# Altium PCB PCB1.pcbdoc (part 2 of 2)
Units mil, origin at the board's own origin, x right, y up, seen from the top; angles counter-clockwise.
Board outline 26305 x 7340 mil, 4 copper layers (Top Layer, Inner1, Inner2, Bottom Layer); 215 components, 225 nets, 1133 pads, 8 vias.
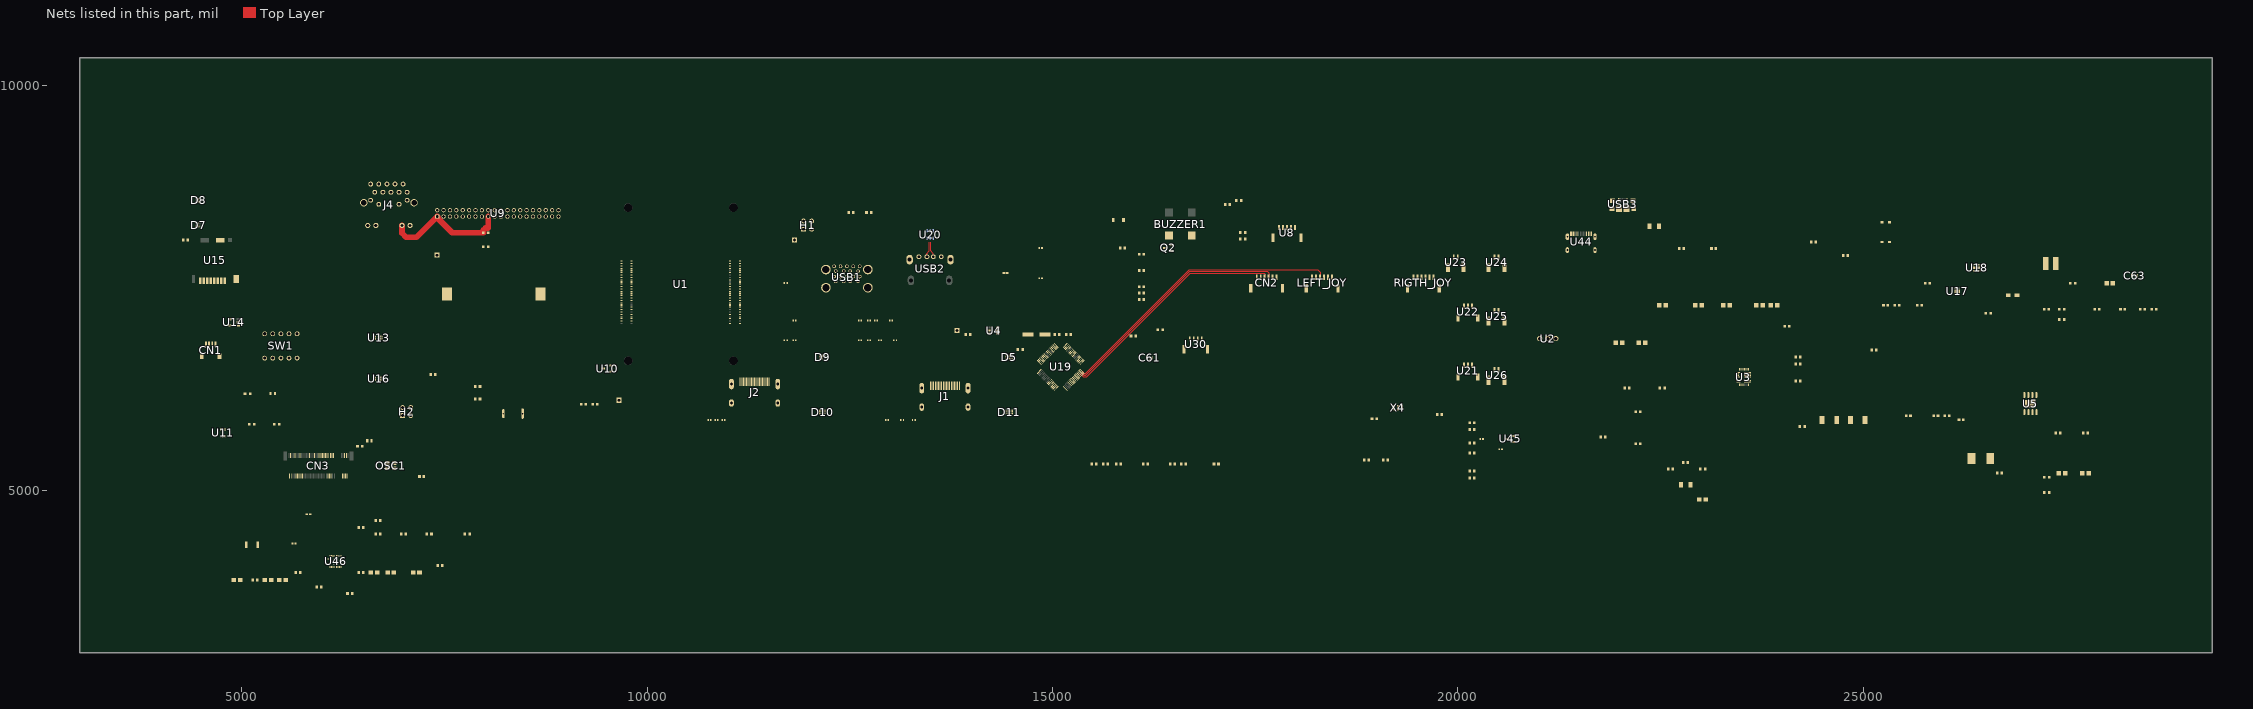
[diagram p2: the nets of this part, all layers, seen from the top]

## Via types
v1: diameter 15.75, hole 7.87, Top Layer to Bottom Layer, 8 vias

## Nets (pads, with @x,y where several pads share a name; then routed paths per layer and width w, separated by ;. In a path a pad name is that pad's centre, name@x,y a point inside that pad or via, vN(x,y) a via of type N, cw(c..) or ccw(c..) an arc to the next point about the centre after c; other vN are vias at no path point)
5V_USB3.0: C20.1 C21.2 C22.2 C64.1 U4.6 U20.5 USB1.1 USB1.10 USB2.1
$1N18: J1.14
$1N31: J2.14
$1N87: U1.141
$1N88: U1.139
$1N121: R8.2 U4.5
$1N122: U1.107 U1.113 U1.119 U1.125 U1.131 U1.137 U1.155 U1.161 U1.167 U1.173 U1.179 U1.185 U1.191 U1.197
$1N155: R36.2 U20.4
$1N156: R37.1 U20.6
$2N9: R1.2 U3.25
$2N10: C5.2 R1.1
$2N12: C6.2 R2.2 U3.2
$2N29: R4.2 U3.5
$2N30: C10.1 R5.2 U3.30
$2N31: C10.2 R6.2 U3.29
$2N37: C12.2 U3.26
$2N45: D1.1 U44.A4B9 U44.B4A9
$2N54: C50.2 D2.1 D3.1 U18.2 U18.3
$2N57: L4.1 U18.9
$2N58: C51.2 C63.1 L4.2 R30.2 U18.10
$2N59: R30.1 U18.7
$2N68: L1.1 U17.6
$2N83: C23.2 U5.4
$2N84: C26.2 U5.3
$2N89: C30.2 U5.7
$2N91: C30.1 L3.1 U5.6
$2N3270: C67.2 U46.10
$2N3397: C68.2 U46.8
$2N3401: C68.1 R41.1 U46.4 U46.5 U46.6 U46.7 U47.2
$2N3574: R41.2 U46.3
$2N3583: R42.2 U46.19
$2N4443: C77.2 U46.1
$2N4479: C80.2 R43.1 U46.18
$2N4576: C75.1 R43.2
$2N4875: C69.2 C71.2 C74.2 C79.2 R47.1 U46.14 U46.15 U46.16
$2N4890: R44.1 R45.1 R46.1 R47.2 U46.17 U48.1
$3N7: U1.18
$3N25: U1.64
$3N62: J3.1 U1.73
$3N114: R11.2 RED_LED.2
$3N115: R11.1 U11.4
$3N118: GREEN_LED.2 R13.2
$3N153: C40.2 J4.4 J4.5
$3N161: J4.16 R23.1
$3N162: J4.18 R24.2
$3N198: CN3.10 R31.2
$3N199: GREEN_LED1.2 R31.1
$3N203: CN3.68 OSC1.3
$4N7: U19.5 X4.1
$4N8: U19.6 X4.3
$4N9: R28.2 U19.60
$4N11: R29.2 U19.7
$4N13: C59.2 U19.47
$4N14: C60.2 U19.31
$4N18: C61.1 U30.1
$4N99: R12.2 R19.2 U45.1
$4N103: Q2.1 R40.2
$4N108: BUZZER1.2 D4.2 Q2.3
$4N114: R20.2 U8.3
$4N115: R34.2 U8.2
+1.8V: R22.1 U1.88 U1.90
+3.3V: GREEN_LED.1 J4.15 J4.17 R21.1 RED_LED.1 U1.84 U1.86 U9.1 U9.17 U11.5 U14.5 U19.8 U46.2 | length 1562.8
  Top Layer w70.87: J4.17@6976.02,8270.08 6974.89,8268.95 6974.89,8175.11 7025,8125 7156.14,8125 U9.1@7410.41,8379.27 7422.14,8367.54 7422.14,8351.52 7594.96,8178.7 R21.1@7978.78,8178.7 7980.81,8180.73 7980.81,8212.86 8005.07,8237.12 8037.2,8237.12 8040.33,8240.25 U9.17@8040.33,8379.27
+5V_RT: C31.2 C32.2 C33.2 C41.2 C42.2 C43.2 L3.2 R9.2 U12.1 U17.3 USB3.1
ACOK: R16.1 U3.28 U19.10
ADC1_IN0: C34.1 CN2.3 U19.14 | length 2875.4
  Top Layer w10: U19.14@15337.06,6441.72 15376.57,6402.21 15419.19,6402.21 15940.7,6923.72 15940.7,6928.14 15947.13,6934.58 15951.55,6934.58 16700,7683.02 17609.52,7683.02 17616.59,7675.95 CN2.3@17616.59,7632.48
ADC1_IN1: C35.1 CN2.4 U19.15 | length 2918.7
  Top Layer w10: U19.15@15350.98,6455.63 15384.72,6421.89 15411.03,6421.89 16691.85,7702.7 17647.2,7702.7 17665.8,7684.1 CN2.4@17665.8,7632.48
ADC1_IN2: C36.1 LEFT_JOY.3 U19.16 | length 3549.6
  Top Layer w10: U19.16@15364.9,6469.56 15392.88,6441.58 15402.88,6441.58 16683.69,7722.39 18270.04,7722.39 18300.18,7692.26 LEFT_JOY.3@18300.18,7632.48
ADC1_IN3: C62.1 LEFT_JOY.4 U19.17
ADC1_IN4: C38.1 RIGTH_JOY.3 U19.20
ADC1_IN5: C37.1 RIGTH_JOY.4 U19.21
AGND: B1.2 C1.1 C2.1 C3.1 C4.1 C5.1 C6.1 C11.1 C12.1 C13.1 C14.1 C15.1 C16.1 C17.1 C18.1 C19.1 C20.2 C21.1 C22.1 C23.1 C24.1 C25.1 C26.1 C27.1 C28.1 C29.1 C32.1 C33.1 C34.2 C35.2 C36.2 C37.2 C38.2 C39.1 C40.1 C41.1 C42.1 C43.1 C45.1 C46.1 C47.1 C48.1 C49.1 C50.1 C51.1 C52.1 C53.1 C54.1 C55.1 C56.1 C57.1 C58.1 C59.1 C60.1 C61.2 C62.2 C63.2 C64.2 C65.1 C66.2 C67.1 C69.1 C70.1 C71.1 C72.1 C73.1 C74.1 C75.2 C77.1 C78.1 C79.1 C80.1 CN1.2 CN1.5 CN1.6 CN2.5 CN2.6 CN2.7 CN2.8 CN3.3 CN3.9 CN3.15 CN3.27 CN3.33 CN3.39 CN3.45 CN3.51 CN3.57 CN3.71 CN3.73 D5.3 D5.8 D7.3 D7.8 D8.3 D8.8 D9.3 D9.8 D10.3 D10.8 D11.3 D11.8 J1.2 J1.5 J1.8 J1.11 J1.17 J1.SH1 J1.SH2 J1.SH3 J1.SH4 J2.2 J2.5 J2.8 J2.11 J2.17 J2.SH1 J2.SH2 J2.SH3 J2.SH4 J4.S1 J4.S2 LEFT_JOY.5 LEFT_JOY.6 LEFT_JOY.7 LEFT_JOY.8 OSC1.2 Q2.2 R3.2 R4.1 R8.1 R10.1 R19.1 R25.1 R27.1 R28.1 R39.2 R42.1 R44.2 R45.2 R46.2 RIGTH_JOY.5 RIGTH_JOY.6 RIGTH_JOY.7 RIGTH_JOY.8 SW1.1 SW1.2 SW1.3 SW1.4 SW1.5 TP2.1 U1.1 U1.2 U1.7 U1.8 U1.13 U1.14 U1.22 U1.23 U1.32 U1.33 U1.42 U1.43 U1.52 U1.53 U1.59 U1.60 U1.65 U1.66 U1.71 U1.74 U1.98 U1.108 U1.114 U1.120 U1.126 U1.132 U1.138 U1.144 U1.150 U1.156 U1.162 U1.168 U1.174 U1.180 U1.186 U1.192 U1.198 U2.1 U3.4 U3.19 U3.27 U4.2 U5.5 U5.9 U6.1 U7.1 U8.1 U8.4 U8.6 U8.7 U9.6 U9.9 U9.14 U9.20 U9.25 U9.30 U9.34 U9.39 U10.3 U11.3 U13.3 U13.8 U14.2 U15.6 U15.9 U15.10 U16.3 U16.8 U17.4 U17.8 U17.9 U18.1 U18.4 U18.5 U18.6 U18.11 U19.12 U19.18 U19.63 U20.2 U21.2 U21.4 U21.5 U22.2 U22.4 U22.5 U23.2 U23.3 U23.4 U24.2 U24.3 U24.4 U25.2 U25.3 U25.4 U26.2 U26.3 U26.4 U27.1 U28.1 U29.1 U30.2 U30.5 U30.6 U31.1 U32.1 U33.1 U34.1 U35.1 U36.1 U37.1 U38.1 U39.1 U40.1 U41.1 U42.1 U43.1 U44.1 U44.2 U44.3 U44.4 U44.A1B12 U44.B1A12 U45.2 U46.11 U46.12 U46.20 U46.21 U48.2 USB1.4 USB1.7 USB1.13 USB1.16 USB1.19 USB1.20 USB2.4 USB2.5 USB2.6 USB3.5 USB3.6 X4.2
  other v1: 6135.86,4095.12 6177.2,4095.12 6106.33,4125.63 6135.86,4125.63 6177.2,4125.63 6206.73,4125.63 6135.86,4156.14 6177.2,4156.14
BST1: C7.2 U3.23
BST2: C8.2 U3.24
BST3: C9.2 U3.15
BT_NDISABLE: SW1.6 U1.91
CC1: U1.94 U44.A5
CC2: U1.96 U44.B5
CM5_GPIO_IN: U1.25 U9.40 U19.9
CM_5V: C1.2 C19.2 C65.2 CN1.4 TP1.1 U1.77 U1.79 U1.81 U1.83 U1.85 U1.87 U4.1 U9.2 U9.4 U10.1 U12.2
D+: U20.1 USB2.3 | length 189.9
  Top Layer w10: 13497.38,8060.91 13497.38,7955.33 13528.75,7923.96 USB2.3@13528.75,7883.96
D-: U20.3 USB2.2 | length 189.9
  Top Layer w10: USB2.2@13450.01,7883.96 13450.01,7923.96 13481.38,7955.33 13481.38,8060.91
EEPROM_NWP: SW1.9 U1.20
EN_5V: U5.1 U19.25
ETH_LEDG: R24.1 U1.17
ETH_LEDY: R23.2 U1.15
FB: C44.1 R26.1 R27.2 U17.1
FB1: C31.1 R9.1 R10.2 U5.2
GPIO2: U1.58 U9.3
GPIO3: U1.56 U9.5
GPIO4: U1.54 U9.7
GPIO5: U1.34 U9.29
GPIO6: U1.30 U9.31
GPIO7: U1.37 U9.26
GPIO8: U1.39 U9.24
GPIO9: U1.40 U9.21
GPIO10: U1.44 U9.19
GPIO11: U1.38 U9.23
GPIO12: U1.31 U9.32
GPIO13: U1.28 U9.33
GPIO14: U1.55 U9.8 U19.42
GPIO15: U1.51 U9.10 U19.43
GPIO16: U1.29 U9.36 U19.45
GPIO17: U1.50 U9.11 U19.44
GPIO18: U1.49 U9.12
GPIO19: U1.26 U9.35
GPIO20: U1.27 U9.38
GPIO22: U1.46 U9.15
GPIO23: U1.47 U9.16
GPIO24: U1.45 U9.18
GPIO25: U1.41 U9.22
GPIO26: U1.24 U9.37
GPIO27: U1.48 U9.13
GPIO_IN0: U19.61 U21.1
GPIO_IN1: U19.62 U21.3
GPIO_IN2: U19.29 U22.1
GPIO_IN3: U19.30 U22.3
GPIO_IN4: U19.33 U23.1
GPIO_IN5: U19.34 U24.1
GPIO_IN6: U19.35 U25.1
GPIO_IN7: U19.36 U26.1
GPIO_VREF: R14.2 R15.2 R21.2 R22.2 U1.78
HDMI0_CEC: J1.13 U1.151 U42.2
HDMI0_CK_N: D11.5 D11.6 J1.12 U1.190
HDMI0_CK_P: D11.4 D11.7 J1.10 U1.188
HDMI0_D0_N: D11.2 D11.9 J1.9 U1.184
HDMI0_D0_P: D11.1 D11.10 J1.7 U1.182
HDMI0_D1_N: D5.5 D5.6 J1.6 U1.178
HDMI0_D1_P: D5.4 D5.7 J1.4 U1.176
HDMI0_D2_N: D5.2 D5.9 J1.3 U1.172
HDMI0_D2_P: D5.1 D5.10 J1.1 U1.170
HDMI0_HOTPLUG: J1.19 U1.153
HDMI0_SCL: J1.15 U1.200 U43.2
HDMI0_SDA: J1.16 U1.199 U41.2
HDMI1_CEC: J2.13 U1.149 U7.2
HDMI1_CK_N: D10.5 D10.6 J2.12 U1.166
HDMI1_CK_P: D10.4 D10.7 J2.10 U1.164
HDMI1_D0_N: D10.2 D10.9 J2.9 U1.160
HDMI1_D0_P: D10.1 D10.10 J2.7 U1.158
HDMI1_D1_N: D9.5 D9.6 J2.6 U1.154
HDMI1_D1_P: D9.4 D9.7 J2.4 U1.152
HDMI1_D2_N: D9.2 D9.9 J2.3 U1.148
HDMI1_D2_P: D9.1 D9.10 J2.1 U1.146
HDMI1_HOTPLUG: J2.19 U1.143
HDMI1_SCL: J2.15 U1.147 U6.2
HDMI1_SDA: J2.16 U1.145 U40.2
HDMI_5V: C2.2 J1.18 J2.18 TP3.1 U10.2
I2C1_SCL: R33.1 U3.11 U19.58
I2C1_SDA: R32.1 U3.10 U19.59
ID_SC: H1.1 U1.35 U9.28
ID_SD: H1.3 U1.36 U9.27
IN: C11.2 R5.1 R7.1 U3.1 U3.22
INT: R18.1 U3.9 U19.24
LED_GREEN: R34.1 U19.40
LED_NACT: R13.1 U1.21
LED_RED: R20.1 U19.39
M2_3V3: C44.2 C45.2 C46.2 C47.2 C48.2 C52.2 CN3.2 CN3.4 CN3.12 CN3.14 CN3.16 CN3.18 CN3.70 CN3.72 CN3.74 GREEN_LED1.1 L1.2 OSC1.1 OSC1.4 R26.2
MCU_3V3: BUZZER1.1 C49.2 C53.2 C54.2 C55.2 C56.2 C57.2 C58.2 C63.3 CN2.1 CN2.2 D4.1 LEFT_JOY.1 LEFT_JOY.2 R16.2 R17.2 R18.2 R29.1 R32.2 R33.2 R35.2 R38.1 RIGTH_JOY.1 RIGTH_JOY.2 U18.8 U19.1 U19.13 U19.19 U19.32 U19.48 U19.64
NPWR_LED: U1.95 U11.2
NRPIBOOT: SW1.10 U1.93
NTC: R2.1 R3.1 U2.2 U3.3
OFF/ON_CM5: R12.1 U19.26
PCIE_CLK_N: CN3.53 U1.112
PCIE_CLK_P: CN3.55 U1.110
PCIE_NCLKREQ: CN3.52 U1.102
PCIE_NRST: CN3.50 U1.109
PCIE_NWAKE: CN3.54 U1.104
PCIE_PWR_EN: R25.2 U1.106 U17.7
PCIE_RX_N: CN3.43 U1.118
PCIE_RX_P: CN3.41 U1.116
PCIE_TX_N: CN3.49 U1.124
PCIE_TX_P: CN3.47 U1.122
PROCHOT: R17.1 U3.8 U19.11
PWM: CN1.3 U1.19
PWR_BUT: U1.92 U45.3
PWRB_STM32: C66.1 R35.1 U8.5 U19.37
SCL1: H1.2 R15.1
SD_CLK: D7.2 U1.57 U15.5
SD_CMD: D7.1 U1.62 U15.3
SD_DAT0: D7.4 U1.63 U15.7
SD_DAT1: D7.5 U1.67 U15.8
SD_DAT2: D8.2 U1.69 U15.1
SD_DAT3: D8.4 U1.61 U15.2
SD_PWR: C39.2 U14.1 U15.4
SD_PWR_ON: U1.75 U14.4
SDA1: H1.4 R14.1
SW1: C7.1 L5.2 U3.21
SW2: C8.1 L2.2 U3.20
SW3: C9.1 L2.1 L5.1 U3.18
SWCLK: R39.1 U19.49 U30.4
SWD_5V: C61.3 D3.2
SWDIO: R38.2 U19.46 U30.3
SYS: C13.2 C14.2 C15.2 C16.2 C17.2 C27.2 C28.2 C29.2 D2.2 U3.6 U3.17 U5.8
TACHO: CN1.1 U1.16
TIM3_CH4: R40.1 U19.27
TR0_TAP: H2.3 J4.11
TR1_TAP: H2.1 J4.12
TR2_TAP: H2.2 J4.13
TR3_TAP: H2.4 J4.14
TRD0_N: J4.2 U1.10 U16.4 U16.7
TRD0_P: J4.1 U1.12 U16.5 U16.6
TRD1_N: J4.6 U1.6 U16.2 U16.9
TRD1_P: J4.3 U1.4 U16.1 U16.10
TRD2_N: J4.8 U1.9 U13.4 U13.7
TRD2_P: J4.7 U1.11 U13.5 U13.6
TRD3_N: J4.10 U1.5 U13.2 U13.9
TRD3_P: J4.9 U1.3 U13.1 U13.10
USB2_N: R36.1 U1.103
USB2_P: R37.2 U1.105
USB3-0-D_N: U1.136 U31.2 USB1.2
USB3-0-D_P: U1.134 U27.2 USB1.3
USB3-0-RX_N: U1.128 U37.2 USB1.6
USB3-0-RX_P: U1.130 U36.2 USB1.5
USB3-0-TX_N: U1.140 U38.2 USB1.9
USB3-0-TX_P: U1.142 U39.2 USB1.8
USB3-1-D_N: U1.165 U29.2 USB1.11
USB3-1-D_P: U1.163 U28.2 USB1.12
USB3-1-RX_N: U1.157 U35.2 USB1.15
USB3-1-RX_P: U1.159 U34.2 USB1.14
USB3-1-TX_N: U1.169 U32.2 USB1.18
USB3-1-TX_P: U1.171 U33.2 USB1.17
USBOTG_ID: SW1.8 U1.101
VBAT: B1.1 C3.2 C4.2 C70.2 C72.2 C73.2 C78.2 U1.76 U2.3 U3.7 U3.16 U46.9 U47.1
VBUS: C18.2 C24.2 C25.2 D1.2 R6.1 R7.2
VBUS_EN: U1.111 U4.3
WIFI_NDISABLE: SW1.7 U1.89
pads on no net: BUZZER1.3 BUZZER1.4 CN3.1 CN3.5 CN3.6 CN3.7 CN3.8 CN3.11 CN3.13 CN3.17 CN3.19 CN3.20 CN3.21 CN3.22 CN3.23 CN3.24 CN3.25 CN3.26 CN3.28 CN3.29 CN3.30 CN3.31 CN3.32 CN3.34 CN3.35 CN3.36 CN3.37 CN3.38 CN3.40 CN3.42 CN3.44 CN3.46 CN3.48 CN3.56 CN3.58 CN3.67 CN3.69 CN3.75 CN3.76 D7.6 D7.7 D7.9 D7.10 D8.1 D8.5 D8.6 D8.7 D8.9 D8.10 U1. U1.68 U1.70 U1.72 U1.80 U1.82 U1.97 U1.99 U1.100 U1.115 U1.117 U1.121 U1.123 U1.127 U1.129 U1.133 U1.135 U1.175 U1.177 U1.181 U1.183 U1.187 U1.189 U1.193 U1.194 U1.195 U1.196 U3.12 U3.13 U3.14 U4.4 U11.1 U14.3 U15.11 U15.12 U15.13 U17.2 U17.5 U19.2 U19.3 U19.4 U19.22 U19.23 U19.28 U19.38 U19.41 U19.50 U19.51 U19.52 U19.53 U19.54 U19.55 U19.56 U19.57 U44.A6 U44.A7 U44.A8 U44.B6 U44.B7 U44.B8 U46.13 USB2.7 USB2.8 USB3.2 USB3.3 USB3.4

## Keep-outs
Board Outline Layer:
  the board outline again, w10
